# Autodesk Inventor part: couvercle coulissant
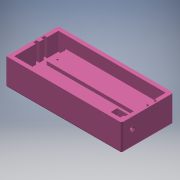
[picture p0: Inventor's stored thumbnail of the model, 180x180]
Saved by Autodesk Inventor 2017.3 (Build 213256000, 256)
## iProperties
Part Number: couvercle coulissant
Material: Plastique ABS
Document SubType Name: Modeling
Designer: ficho
Density: 1.06 g/cm^3
Appearance: Rose
Mass: 122.179 g
Surface Area: 370.426 cm^2
Volume: 115.263 cm^3
Author: ficho
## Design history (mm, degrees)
sketch "Esquisse2"
  geometry: L1 (-123, 0)-(0, 0); L2 (0, 0)-(0, 25); L3 (0, 25)-(3, 25); L4 (3, 25)-(3, 28); L5 (3, 28)-(0, 28); L6 (0, 28)-(0, 34); L7 (0, 34)-(3, 34); L8 (3, 34)-(3, 37); L9 (3, 37)-(0, 37); L10 (0, 37)-(0, 50); L11 (0, 50)-(-123, 50); L12 (-123, 50)-(-123, 37); L13 (-123, 37)-(-126, 37); L14 (-126, 37)-(-126, 34); L15 (-126, 34)-(-123, 34); L16 (-123, 34)-(-123, 28); L17 (-123, 28)-(-126, 28); L18 (-126, 28)-(-126, 25); L19 (-126, 25)-(-123, 25); L20 (-123, 25)-(-123, 0); L21 (-10, 5)-(-10, 11.275); L22 (-32, 5)-(-10, 5); L23 (-102.4, 13.962)-(-102.4, 15.2); L24 (-103.6, 15.2)-(-103.6, 13.962); L25 (-102.4, 4.8)-(-102.4, 5.962); L26 (-103.6, 5.962)-(-103.6, 4.8); L27 (-103.6, 4.8)-(-102.4, 4.8); L28 (-102.4, 15.2)-(-103.6, 15.2); L29 (-123, 50)-(-128, 50); L30 (-128, 50)-(-128, 0); L31 (-128, 0)-(-123, 0); L32 (-123, 0)-(-123, 50); L33 (0, 50)-(5, 50); L34 (5, 50)-(5, 0); L35 (5, 0)-(0, 0); L36 (0, 0)-(0, 50); L37 (-128, 0)-(5, 0); L38 (5, 0)-(5, -5); L39 (5, -5)-(-128, -5); L40 (-128, -5)-(-128, 0); L41 (-128, 55)-(5, 55); L42 (5, 55)-(5, 50); L43 (5, 50)-(-128, 50); L44 (-128, 50)-(-128, 55); C1 r 4 at (-21, 10); 2 further points
  constraints: 88 end point, 8 parallel, 4 horizontal, 4 perpendicular, 2 point on line, 1 centre point
  dimensions: "d18" = 5 distance of L31.end L30.end; "d19" = 5 distance of L34.end L35.end; "d20" = 5 distance of L37.end L38.end; "d21" = 5 distance between parallel lines of L11 L41
extrude "Extrusion2" new body sketch "Esquisse2" distance "d22" = 10; taper "d23" = 0 deg
sketch "Esquisse3"
  geometry: L1 (0.5, -0.5)-(-123.5, -0.5); L2 (-123.5, 50.5)-(0.5, 50.5); L3 (5, -5)-(5, 55) reference; L4 (-128, -5)-(5, -5) reference; L5 (5, 55)-(-128, 55) reference; L6 (-128, 55)-(-128, -5) reference; L7 (-123, 37)-(-126, 37) reference; L8 (-126, 37)-(-126, 34) reference; L9 (-126, 34)-(-123, 34) reference; L10 (-123, 28)-(-126, 28) reference; L11 (-126, 28)-(-126, 25) reference; L12 (-126, 25)-(-123, 25) reference; L13 (-123.5, 37.5)-(-126.5, 37.5); L14 (-126.5, 37.5)-(-126.5, 33.5); L15 (-126.5, 33.5)-(-123.5, 33.5); L16 (-123.5, 28.5)-(-126.5, 28.5); L17 (-126.5, 28.5)-(-126.5, 24.5); L18 (-126.5, 24.5)-(-123.5, 24.5); L19 (3, 37)-(0, 37) reference; L20 (3, 34)-(3, 37) reference; L21 (0, 34)-(3, 34) reference; L22 (3, 28)-(0, 28) reference; L23 (3, 25)-(3, 28) reference; L24 (0, 25)-(3, 25) reference; L25 (0.5, 37.5)-(3.5, 37.5); L26 (3.5, 37.5)-(3.5, 33.5); L27 (3.5, 33.5)-(0.5, 33.5); L28 (0.5, 28.5)-(3.5, 28.5); L29 (3.5, 28.5)-(3.5, 24.5); L30 (3.5, 24.5)-(0.5, 24.5); L31 (-123.5, 37.5)-(-123.5, 50.5); L32 (-123.5, -0.5)-(-123.5, 24.5); L33 (-123.5, 28.5)-(-123.5, 33.5); L34 (0.5, 50.5)-(0.5, 37.5); L35 (0.5, 33.5)-(0.5, 28.5); L36 (0.5, 24.5)-(0.5, -0.5); 1 further point
  constraints: 40 end point, 10 parallel, 3 perpendicular, 1 horizontal
  dimensions: "d25" = 4.5 distance between parallel lines of L4 L1 (= d24); "d26" = 4.5 distance between parallel lines of L2 L5 (= d24); "d28" = 0.5 distance between parallel lines of L7 L13; "d29" = 0.5 distance between parallel lines of L10 L16; "d30" = 0.5 distance between parallel lines of L19 L25; "d31" = 0.5 distance between parallel lines of L22 L28
extrude "Extrusion3" join sketch "Esquisse3" distance "d32" = 21; taper "d33" = 0 deg
sketch "Esquisse4"
  geometry: L1 (-32, 5)-(-10, 5) reference; L2 (-10, 5)-(-32, 5); L3 (-32, 5)-(-32, 27); L4 (-32, 27)-(-10, 27); L5 (-10, 27)-(-10, 5); L6 (-9, 28)-(-33, 28); L7 (-33, 28)-(-33, 4); L8 (-33, 4)-(-9, 4); L9 (-9, 4)-(-9, 28); 1 further point
  constraints: 16 end point, 4 parallel, 2 perpendicular, 1 horizontal, 3 other
  dimensions: "d34" = 22 distance of L2.end L3.end; "d37" = 1 distance between parallel lines of L4 L6
extrude "Extrusion4" cut sketch "Esquisse4" distance "d35" = 8; taper "d36" = 0 deg
sketch "Esquisse6"
  geometry: L1 (-25.5, 18.5)-(-25.5, 27.5); L2 (-14.104, 5.5)-(-9.5, 5.5); L3 (-24.493, 16.043)-(-14.104, 5.5); L4 (-9, 27.5)-(-9, 28); L5 (-9, 28)-(-25.5, 28); L6 (-25.5, 28)-(-25.5, 27.5); L7 (-9.5, 5.5)-(-9, 5.5); L8 (-9, 5.5)-(-9, 27.5); A1 r 3.5 centre (-22, 18.5) between (-25.5, 18.5) and (-24.493, 16.043); 3 further points
  constraints: 16 end point, 2 point on circle, 1 centre point, 1 coincident, 1 parallel
extrude "Extrusion6" join sketch "Esquisse6" distance "d56" = 4.5; taper "d57" = 0 deg
sketch "Esquisse7"
  geometry: L1 (-11.95, 19.5)-(-11.95, 16.5); L2 (-13.2, 19.5)-(-13.2, 16.5); L3 (-10.7, 16.5)-(-10.7, 19.5); A1 r 3.5 centre (-22, 18.5) between (-25.5, 18.5) and (-24.493, 16.043) reference; A2 r 1.25 centre (-11.95, 19.5) between (-10.7, 19.5) and (-13.2, 19.5); A3 r 1.25 centre (-11.95, 16.5) between (-13.2, 16.5) and (-10.7, 16.5); 2 further points
  constraints: 8 end point, 4 point on circle, 4 tangent, 2 centre point, 1 midpoint, 1 parallel, 1 vertical
  dimensions: "d58" = 10.05 horizontal distance of point (-11.95, 18) A1.centre; "d59" = 0.5 vertical distance of A1.centre point (-11.95, 18); "d60" = 3 distance of L1.end L1.start; "d61" = 1.25 radius of A3
extrude "Extrusion7" cut sketch "Esquisse7" stored distance "d62" = 4.5; taper "d63" = 30 deg
sketch "Esquisse8"
  geometry: A1 r 3.5 centre (-22, 18.5) between (-25.5, 18.5) and (-24.493, 16.043) reference; 1 further point
hole "Perçage1" sketch "Esquisse8" at (-22, 18.5) diameter "d64" = 1; stored, may be unused: countersink angle "d68" = 90 deg, drill point angle "d70" = 118 deg; dims "d65" = 6, "d66" = 4, "d67" = 2, "d69" = 3
fillet "Congé1" dims "d71" = 2
sketch "Esquisse9"
  geometry: C1 r 6.15 at (103.6, 10.1) reference; 1 further point
extrude "Extrusion8" cut sketch "Esquisse9" stored distance "d72" = 4.5; taper "d73" = 0 deg
sketch "Esquisse10"
  geometry: C1 r 7 at (-103.6, 10.1) reference; 1 further point
extrude "Extrusion9" cut sketch "Esquisse10" distance "d74" = 8; taper "d75" = 0 deg
sketch "Esquisse11"
  geometry: L1 (128, -17)-(5, -17); L2 (5, -17)-(5, -14); L3 (5, -14)-(128, -14); L4 (128, -14)-(128, -17); L5 (133, 0)-(133, -31) reference; L6 (0, 0)-(0, -31) reference; L7 (133, -31)-(0, -31) reference; L8 (0, 0)-(133, 0) reference; 1 further point
  constraints: 8 end point, 2 parallel, 1 horizontal, 1 perpendicular
  dimensions: "d76" = 3 distance of L1.end L2.end; "d77" = 5 distance between parallel lines of L4 L5; "d78" = 5 distance between parallel lines of L6 L2 (= d77); "d79" = 14 distance between parallel lines of L1 L7; "d80" = 14 distance between parallel lines of L8 L3 (derived)
extrude "Extrusion10" cut sketch "Esquisse11" distance "d81" = 3; taper "d82" = 0 deg
sketch "Esquisse12"
  geometry: L1 (128, -17)-(5, -17) reference; L2 (128, -14)-(128, -17) reference; L3 (5, -14)-(128, -14) reference; L4 (5, -17)-(5, -14) reference; L5 (11, -17)-(11, -14); L6 (122, -17)-(122, -14); L7 (11, -17)-(122, -17); L8 (122, -17)-(122, -14); L9 (122, -14)-(11, -14); L10 (11, -14)-(11, -17); 1 further point
  constraints: 12 end point, 4 point on line, 3 parallel, 2 perpendicular, 1 horizontal
  dimensions: "d83" = 6 distance between parallel lines of L5 L4; "d84" = 6 distance between parallel lines of L2 L6 (= d83)
extrude "Extrusion11" cut sketch "Esquisse12" distance "d85" = 50; taper "d86" = 0 deg
sketch "Esquisse13"
  geometry: L1 (-117, 52)-(-117, 24) reference; L2 (-123.5, 50.5)-(0.5, 50.5) reference; L3 (-6, 24)-(-6, 52) reference; L4 (0.5, 50.5)-(-123.5, 50.5) reference; L5 (-117, 50.5)-(-6, 50.5); L6 (-6, 50.5)-(-6, 30.5); L7 (-6, 30.5)-(-117, 30.5); L8 (-117, 30.5)-(-117, 50.5); 1 further point
  constraints: 8 end point, 3 point on line, 2 parallel, 1 horizontal, 1 perpendicular
  dimensions: "d87" = 20 distance between parallel lines of L7 L2
  node "Référence3"
  node "Référence4"
node "Plan de construction1"
extrude "Extrusion12" join sketch "Esquisse13" stored distance "d88" = 3; taper "d89" = 0 deg
sketch "Esquisse14"
  geometry: C1 r 1.5 at (11, -17) reference; C2 r 1.5 at (112, -17) reference; 1 further point
hole "Perçage2" sketch "Esquisse14" at (112, -17), (11, -17) diameter "d90" = 2; stored, may be unused: countersink angle "d94" = 90 deg, drill point angle "d96" = 118 deg; dims "d91" = 6, "d92" = 4, "d93" = 2, "d95" = 3
fillet "Congé2" dims "d97" = 2
sketch "Esquisse15"
  geometry: L1 (-29, 0)-(-29, 56) reference; L2 (-29, -2)-(0, -2) reference; C1 r 1.5 at (-16.5, 10.5)
  constraints: 1 centre point
  dimensions: "d98" = 3 diameter of C1; "d99" = 12.5 distance from line of C1.centre L1; "d100" = 12.5 distance from line of C1.centre L2 (= d99)
extrude "Extrusion13" cut sketch "Esquisse15" stored distance "d101" = 3; taper "d102" = 0 deg
sketch "Esquisse16"
  geometry: C1 r 1.5 at (16.5, 12.5) reference
hole "Perçage3" sketch "Esquisse16" at (16.5, 12.5) diameter "d103" = 2; stored, may be unused: countersink angle "d107" = 90 deg, drill point angle "d109" = 118 deg; dims "d104" = 6, "d105" = 6, "d106" = 2, "d108" = 3
sketch "Esquisse17"
  geometry: C1 r 1.5 at (-16.5, 10.5) reference
hole "Perçage4" sketch "Esquisse17" at (-16.5, 10.5) diameter "d110" = 2; stored, may be unused: countersink angle "d114" = 90 deg, drill point angle "d116" = 118 deg; dims "d111" = 6, "d112" = 6, "d113" = 2, "d115" = 3
node "Solide2"
node "Référence1"
node "Référence2"
node "Boucle projetée1"
node "Référence5"
node "Référence6"
other parameters: "d24" = 4.5, "d27" = 4.5 (= d24)
